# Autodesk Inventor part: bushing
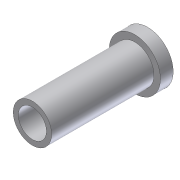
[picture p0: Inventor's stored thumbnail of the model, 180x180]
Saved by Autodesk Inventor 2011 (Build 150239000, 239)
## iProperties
Created: 2009-05
Part Number: bushing
Document SubType Name: Modeling
Designer: Sham
Density: 1 g/cm^3
Author: Sham
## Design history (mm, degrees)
sketch "Sketch1"
  geometry: L1 (5.5, 6)-(10, 6); L2 (10, 6)-(10, 1); L3 (10, 1)-(7.5, 1); L4 (7.5, 1)-(7.5, -39); L5 (7.5, -39)-(5.5, -39); L6 (5.5, -39)-(5.5, 6); L7 (0, 0)-(0, -45)
  constraints: 14 end point, 6 perpendicular, 1 horizontal, 1 other
  dimensions: "d0" = 5 distance of L1.end L2.end; "d1" = 40 distance of L3.end L4.end; "d5" = 10 distance from line of L7.start L2; "d6" = 5.5 distance from line of L7.start L6; "d7" = 15 diameter of L4 L7
revolve "Revolution1" sketch "Sketch1" stored, may be unused: angle "d8" = 90 deg
body "Solid1"
